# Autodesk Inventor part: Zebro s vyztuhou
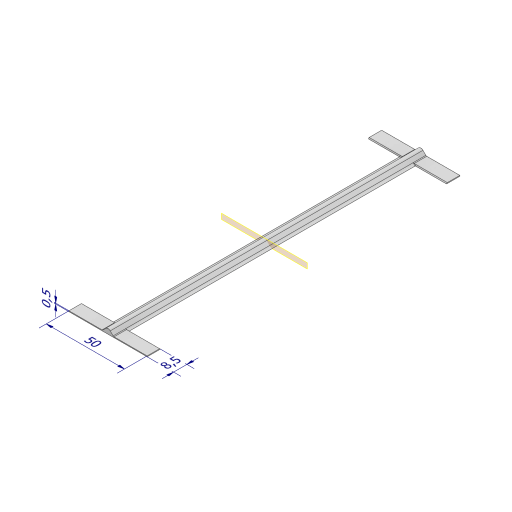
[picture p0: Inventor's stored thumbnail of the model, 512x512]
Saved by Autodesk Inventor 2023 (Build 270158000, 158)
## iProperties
Created: 2025-03
Part Number: Zebro s vyztuhou
Material: Všeobecné
Document SubType Name: Modeling
Designer: tomik
Density: 1 g/cm^3
Appearance: Výchozí
Author: tomik
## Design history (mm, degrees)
node "Poznámky"
  node "Přímá kóta 1" dims "d0" = 4, "d1" = 4, "d45" = 50 (derived)
  node "Přímá kóta 2" dims "d0" = 4, "d1" = 4, "d48" = 8.5 (derived)
  node "Přímá kóta 3" dims "d0" = 4, "d1" = 4, "d51" = 0.5 (derived)
sketch "Náčrt1"
  geometry: L1 (0, 0)-(0, 11.016); L2 (0, 0)-(4, 0); L3 (0, 4)-(4, 0); L4 (0, 4)-(-4, 0); L5 (0, 0)-(-4, 0)
  constraints: 10 end point, 1 horizontal, 1 point on line, 1 symmetric about line, 1 vertical
  dimensions: "d0" = 4 distance of L1.start L2.end; "d1" = 4 distance from line of L3.start L2
extrude "Vysunutí1" new body sketch "Náčrt1" distance "d2" = 200; taper "d3" = 0 deg
sketch "Náčrt2"
  geometry: L1 (0, 0)-(9.652, 0); L2 (4, 0)-(0, 4) reference; L3 (4, 0)-(5.036, 0); A1 r 2.5 centre (5.036, 2.5) between (3.268, 0.732) and (5.036, 0)
  constraints: 4 end point, 3 tangent, 2 point on circle, 2 point on line, 1 centre point, 1 collinear, 1 horizontal
  dimensions: "d4" = 5 diameter of A1
extrude "Vysunutí2" join sketch "Náčrt2" distance "d5" = 200; taper "d6" = 0 deg
fillet "Zaoblení1" dims "d7" = 2
mirror "Zrcadlit1"
node "Pracovní rovina1"
node "Pracovní rovina3"
node "Pracovní rovina4"
sketch "Náčrt10"
  geometry: L1 (-5.036, 0)-(19.964, 0); L2 (19.964, 0)-(19.964, 8.5); L3 (19.964, 8.5)-(-5.036, 8.5); L4 (-5.036, 8.5)-(-5.036, 0); L5 (-30.036, 8.5)-(-5.036, 8.5); L6 (-5.036, 0)-(-30.036, 0); L7 (-30.036, 0)-(-30.036, 8.5)
  constraints: 14 end point, 2 parallel, 2 symmetric about line, 1 horizontal, 1 perpendicular
  dimensions: "d30" = 25 distance between parallel lines of L2 L4; "d31" = 8.5 distance between parallel lines of L1 L3
extrude "Vysunutí9" join sketch "Náčrt10" distance "d32" = 0.5; taper "d33" = 0 deg
fillet "Zaoblení4" dims "d34" = 0.8
chamfer "Zkosení1" distance "d35" = 0.5; stored, may be unused: second distance "d36" = 2, angle "d37" = 45 deg
node "Pracovní rovina5"
mirror "Zrcadlit6"
node "Těleso1"
other parameters: "d43" = 7.1767 (derived), "d44" = 4.14966 (derived), "d46" = 0 (derived), "d49" = 0 (derived)
